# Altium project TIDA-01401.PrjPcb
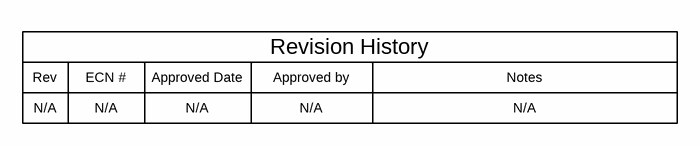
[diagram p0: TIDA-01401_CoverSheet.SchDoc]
CopyrightYear: 2017; PCB_Layout: Zoe Boele; PCB_Rev: E2; PRJ_Customer: Internal Use Only; PRJ_Engineer: Kristen Mogensen; PRJ_Number: TIDA-01401; PRJ_Title: High EMI-Immunity EnDat BoosterPack; SCH_Rev: 1.1; TechSupport: http://www.ti.com/support; TID: 01401
5 sheets, 119 parts. Net scope: global (net labels, ports and power ports of the same name join across sheets).
Board file: TIDA-01401_PCB.PcbDoc
Sheets:
  TIDA-01401_CoverSheet.SchDoc
  TIDA-01401_EVM_Hardware.SchDoc
  TIDA-01401_Interface.SchDoc
  TIDA-01401_PowerSupply.SchDoc
  TIDA-01401_Transceivers.SchDoc

## Sheet TIDA-01401_CoverSheet.SchDoc
size 431 x 279 mm; Date: Not shown in title block; ApprovedBy: Not shown in title block; CheckedBy: Not shown in title block; Author: Not shown in title block; CompanyName: Not shown in title block; Engineer: Not shown in title block; Organization: Not shown in title block; Address1: Not shown in title block; Address2: Not shown in title block; Address3: Not shown in title block; Address4: Not shown in title block; DocumentNumber: 1; Revision: Use project parameter SCH_Rev; SheetNumber: 1; SheetTotal: 3; PageSetup: Record=PageOptions¦CenterHorizontal=True¦CenterVertical=True¦PrintScale=1.00¦XCorrection=1.00¦YCorrection=1.00¦PrintKind=0¦BorderSize=5000000¦LeftOffset=0¦BottomOffset=0¦Orientation=2¦PaperLength=1000¦PaperWidth=1000¦Scale=100¦PaperSource=15¦PrintQuality=600¦MediaType=1¦DitherType=10¦PaperKind=Letter¦PrintScaleMode=1

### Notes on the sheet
- Rev
- N/A
- ECN #
- Approved Date
- Approved by
- Revision History
- Notes

## Sheet TIDA-01401_EVM_Hardware.SchDoc
size 431 x 279 mm; Date: Not shown in title block; ApprovedBy: Not shown in title block; CheckedBy: Not shown in title block; Author: Not shown in title block; CompanyName: Not shown in title block; Engineer: Not shown in title block; Organization: Not shown in title block; Address1: Not shown in title block; Address2: Not shown in title block; Address3: Not shown in title block; Address4: Not shown in title block; DocumentNumber: 1; Revision: Use project parameter SCH_Rev; SheetNumber: 3; SheetTotal: 3; PageSetup: Record=PageOptions¦CenterHorizontal=True¦CenterVertical=True¦PrintScale=1.00¦XCorrection=1.00¦YCorrection=1.00¦PrintKind=0¦BorderSize=5000000¦LeftOffset=0¦BottomOffset=0¦Orientation=2¦PaperLength=1000¦PaperWidth=1000¦Scale=100¦PaperSource=15¦PrintQuality=600¦MediaType=1¦DitherType=10¦PaperKind=Letter¦PrintScaleMode=1
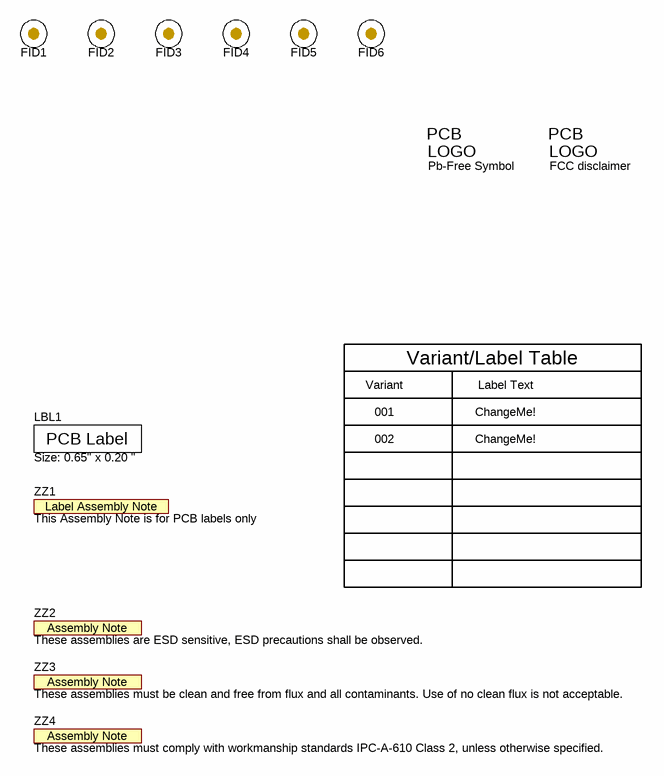
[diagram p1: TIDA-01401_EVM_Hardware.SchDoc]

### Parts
FID1  Fiducial  [Fiducial10-20]  (value not drawn)
FID2  Fiducial  [Fiducial10-20]  (value not drawn)
FID3  Fiducial  [Fiducial10-20]  (value not drawn)
FID4  Fiducial  [Fiducial10-20]  (value not drawn)
FID5  Fiducial  [Fiducial10-20]  (value not drawn)
FID6  Fiducial  [Fiducial10-20]  (value not drawn)
LBL1  Size: 0.65" x 0.20 "  [Label_650x200]
Logo2  Pb-Free Symbol  [Pb-Free_Overlay_Small]  (no BOM)
Logo3  FCC disclaimer  [FCC_disclaimer]  (no BOM)
ZZ1  This Assembly Note is for PCB labels only  [AssemblyNoteLabel]  (no BOM)
ZZ2  These assemblies are ESD sensitive, ESD precautions shall be observed.  [AssemblyNote]  (no BOM)
ZZ3  These assemblies must be clean and free from flux and all contaminants. Use of no clean flux is not acceptable.  [AssemblyNote]  (no BOM)
ZZ4  These assemblies must comply with workmanship standards IPC-A-610 Class 2, unless otherwise specified.  [AssemblyNote]  (no BOM)

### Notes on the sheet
- Variant
- Variant/Label Table
- Label Text
- 001
- 002
- ChangeMe!

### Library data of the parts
FID1-FID6 = Fiducial: Fiducial mark.  There is nothing to buy or mount.; SymbolCreator: codlsc
LBL1 = THT-14-423-10: Thermal Transfer Printable Labels, 0.650" W x 0.200" H - 10,000 per roll; Manufacturer: Brady; SymbolCreator: a0412235; CompType: Label
Logo2 = Pb-Free: SymbolCreator: a0412235
Logo3 = FCC_disclaimer: SymbolCreator: codlsc
ZZ1 = AssemblyNoteLabel: SymbolCreator: a0412235
ZZ2-ZZ4 = AssemblyNote: SymbolCreator: codlsc

## Sheet TIDA-01401_Interface.SchDoc
size 431 x 279 mm; Date: Not shown in title block; ApprovedBy: Not shown in title block; CheckedBy: Not shown in title block; Author: Not shown in title block; CompanyName: Not shown in title block; Engineer: Not shown in title block; Organization: Not shown in title block; Address1: Not shown in title block; Address2: Not shown in title block; Address3: Not shown in title block; Address4: Not shown in title block; DocumentNumber: 1; Revision: Use project parameter SCH_Rev; SheetNumber: 2; SheetTotal: 3; PageSetup: Record=PageOptions¦CenterHorizontal=True¦CenterVertical=True¦PrintScale=0.64¦XCorrection=1.00¦YCorrection=1.00¦PrintKind=0¦BorderSize=5000000¦LeftOffset=0¦BottomOffset=0¦Orientation=2¦PaperLength=1000¦PaperWidth=1000¦Scale=100¦PaperSource=15¦PrintQuality=600¦MediaType=1¦DitherType=10¦PrintScaleMode=1¦PaperKind=8 1/2x11¦PaperIndex=1
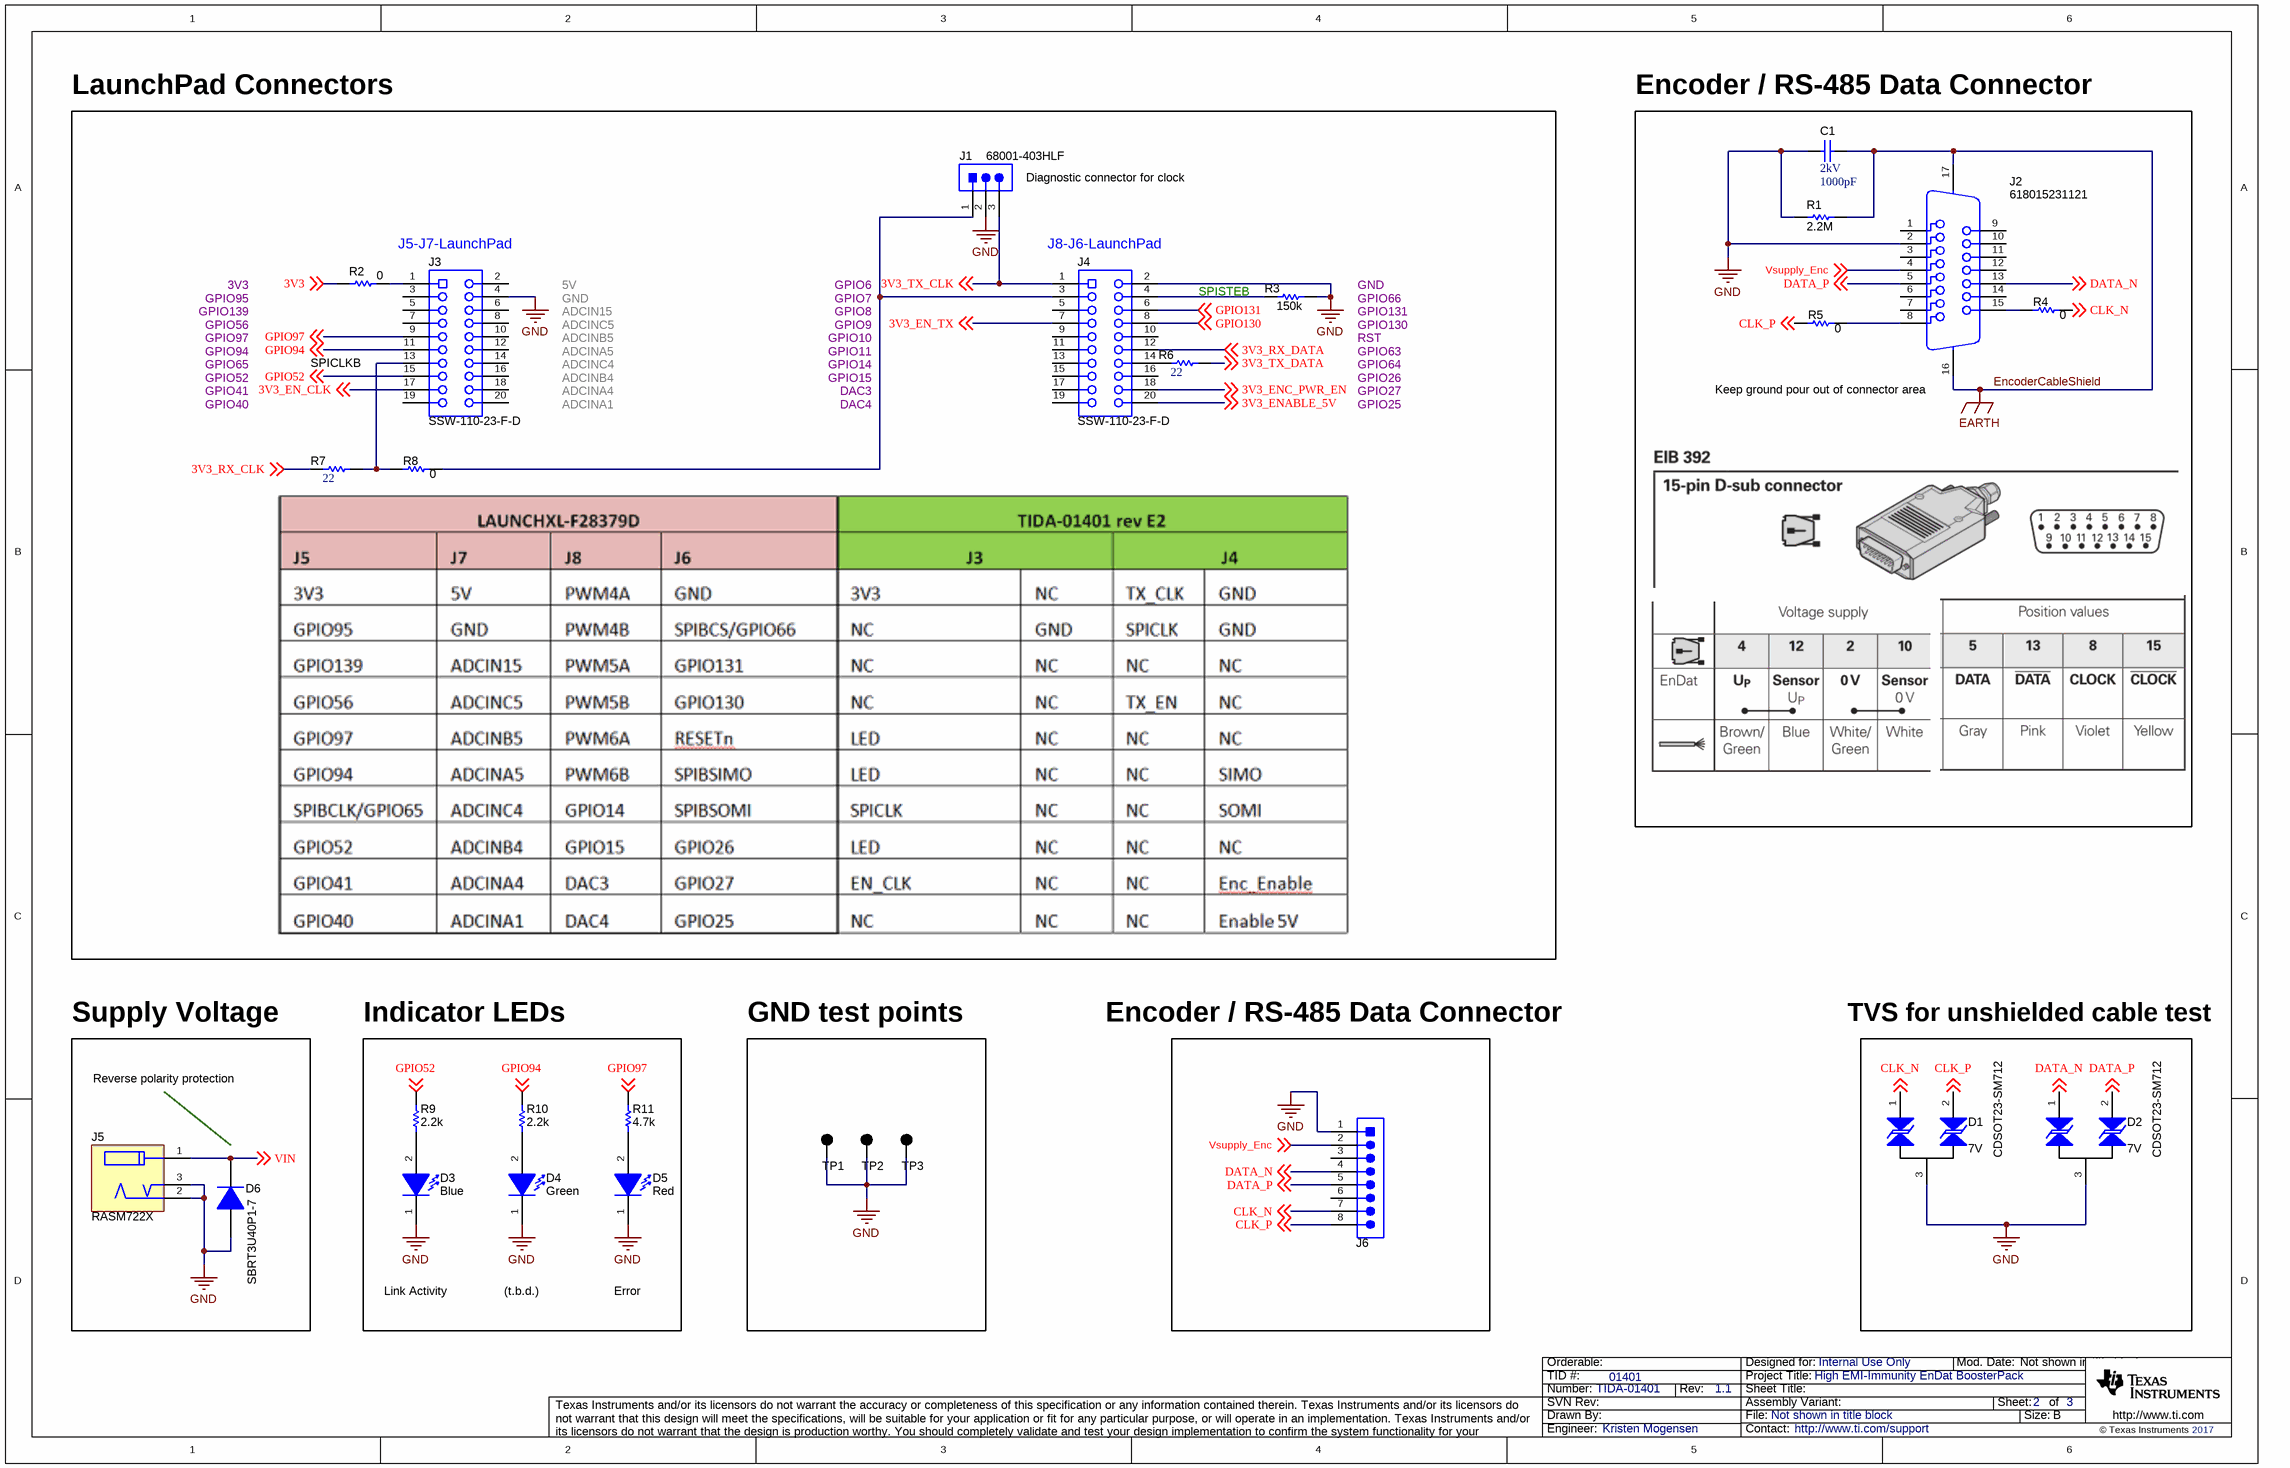
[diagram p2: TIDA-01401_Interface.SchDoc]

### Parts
C1  VDC_V: 2kV  ValueDisplayed: 1000pF  [1812_220]  (hidden comment: 1812GC102KAT1A)
D1  CDSOT23-SM712  value 7V  [SOT-23]
D2  CDSOT23-SM712  value 7V  [SOT-23]
D3  value Blue  [WL-SMCW_Blue]  (hidden comment: 150060BS75000)
D4  value Green  [WL-SMCW_GREEN]  (hidden comment: 150060GS75000)
D5  value Red  [WL-SMCW_RED]  (hidden comment: 150060RS75000)
D6  SBRT3U40P1-7  [PowerDI123]
J1  68001-403HLF  [FCI_68001-403HLF]
J2  618015231121  [Wurth_618015231121]
J3  SSW-110-23-F-D  [CONN_SSW-110-23-F-D]
J4  SSW-110-23-F-D  [CONN_SSW-110-23-F-D]
J5  RASM722X  [Switchcraft_RASM722]
J6  PEC08SAAN  [SULLINS_PEC08SAAN]  (value not drawn)
R1  ValueDisplayed: 2.2M  [1206]  (hidden comment: CRCW12062M20JNEA)
R2  ValueDisplayed: 0  [0603]  (hidden comment: CRCW06030000Z0EA)
R3  ValueDisplayed: 150k  [0402S]  (hidden comment: CRCW0402150KJNED)
R4  ValueDisplayed: 0  [0402S]  (hidden comment: CRCW04020000Z0ED)
R5  ValueDisplayed: 0  [0402S]  (hidden comment: CRCW04020000Z0ED)
R6  ValueDisplayed: 22  [0402S]  (hidden comment: CRCW040222R0JNED)
R7  ValueDisplayed: 22  [0402S]  (hidden comment: CRCW040222R0JNED)
R8  ValueDisplayed: 0  [0402S]  (hidden comment: CRCW04020000Z0ED)
R9  ValueDisplayed: 2.2k  [0402S]  (hidden comment: CRCW04022K20JNED)
R10  ValueDisplayed: 2.2k  [0402S]  (hidden comment: CRCW04022K20JNED)
R11  ValueDisplayed: 4.7k  [0402S]  (hidden comment: CRCW04024K70JNED)
TP1  5001  [Keystone5001]  (value not drawn)
TP2  5001  [Keystone5001]  (value not drawn)
TP3  5001  [Keystone5001]  (value not drawn)

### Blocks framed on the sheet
Keep ground pour out of connector area: C1 J2 R1 R4 R5
Reverse polarity protection: D6 J5

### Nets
EncoderCableShield: C1.1 J2.16(MH1) J2.17(MH2) R1.2  [also labelled EARTH]
GND: C1.2 D1.3 D2.3 D3.1(K) D4.1(K) D5.1(K) D6.2(A) J1.2 J2.2 J3.4 J4.2 J5.2 J5.3 J6.1 R1.1 R3.2 TP1.1 TP2.1 TP3.1
3V3: R2.1 ; off-sheet 3V3
3V3_EN_CLK: J3.17 ; off-sheet 3V3_EN_CLK
3V3_EN_TX: J4.7 ; off-sheet 3V3_EN_TX
3V3_ENABLE_5V: J4.20 ; off-sheet 3V3_ENABLE_5V
3V3_ENC_PWR_EN: J4.18 ; off-sheet 3V3_ENC_PWR_EN
3V3_RX_CLK: R7.1 ; off-sheet 3V3_RX_CLK
3V3_RX_DATA: J4.12 ; off-sheet 3V3_RX_DATA
3V3_TX_CLK: J1.3 J4.1 ; off-sheet 3V3_TX_CLK
3V3_TX_DATA: R6.2 ; off-sheet 3V3_TX_DATA
CLK_N: D1.1 J6.7 R4.2 ; off-sheet CLK_N
CLK_P: D1.2 J6.8 R5.1 ; off-sheet CLK_P
DATA_N: D2.1 J2.13 J6.4 ; off-sheet DATA_N
DATA_P: D2.2 J2.5 J6.5 ; off-sheet DATA_P
GPIO52: J3.15 R9.2 ; off-sheet GPIO52
GPIO94: J3.11 R10.2 ; off-sheet GPIO94
GPIO97: J3.9 R11.2 ; off-sheet GPIO97
GPIO130: J4.8 ; off-sheet GPIO130
GPIO131: J4.6 ; off-sheet GPIO131
VIN: D6.1(K) J5.1 ; off-sheet VIN
Vsupply_Enc: J2.4 J6.2 ; off-sheet Vsupply_Enc
NetD3_2: D3.2(A) R9.1
NetD4_2: D4.2(A) R10.1
NetD5_2: D5.2(A) R11.1
NetJ1_1: J1.1 J4.3 R8.2
NetJ2_8: J2.8 R5.2
NetJ2_15: J2.15 R4.1
NetJ3_1: J3.1 R2.2
NetJ3_13: J3.13 R7.2 R8.1
NetJ4_4: J4.4 R3.1
NetJ4_14: J4.14 R6.1

Not connected (* = marked no-connect by the designer): J2 1 3 6 7 9 10 11 12 14; J3 2 3 5 6 7 8 10 12 14 16 18 19 20; J4 5 9 10 11 13 15 16 17 19; J6 3 6

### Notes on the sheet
- LaunchPad Connectors
- (near C1) Encoder / RS-485 Data Connector
- (near J1) Diagnostic connector for clock
- J5-J7-LaunchPad
- (near J4) J8-J6-LaunchPad
- (near R3) SPISTEB
- SPICLKB
- 3V3
  GPIO95
  GPIO139
  GPIO56
  GPIO97
  GPIO94
  GPIO65
  GPIO52
  GPIO41
  GPIO40
- 5V
  GND
  ADCIN15
  ADCINC5
  ADCINB5
  ADCINA5
  ADCINC4
  ADCINB4
  ADCINA4
  ADCINA1
- GPIO6
  GPIO7
  GPIO8
  GPIO9
  GPIO10
  GPIO11
  GPIO14
  GPIO15
  DAC3
  DAC4
- GND
  GPIO66
  GPIO131
  GPIO130
  RST
  GPIO63
  GPIO64
  GPIO26
  GPIO27
  GPIO25
- Supply Voltage
- Indicator LEDs
- GND test points
- Encoder / RS-485 Data Connector
- TVS for unshielded cable test
- Link Activity
- (t.b.d.)
- Error

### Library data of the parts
C1 = CMP-0064918-2: CAP, CERM, 1000 pF, 2000 V,+/- 10%, X7R, 1812; Manufacturer: AVX; TaMin_C: -55°C; Polarized: N; SizeAreaWB_mm2: 23.1; Value1: Unknown; U/M: EA; Value: 1000pF; TaMax_C: 125°C; SizeZ_mm: 2.2; SizeX_mm: 4.5; SizeY_mm: 3.2; Cap_Case: 1812; Value2: 2000V; SizeArea_mm2: 14.4; CompType: Capacitor; Cap_F: 1nF; AEC Category: Q200
D1 D2 = CDSOT23-SM712: Diode, TVS, Bi, 7 V, SOT-23; Manufacturer: Bourns; SymbolCreator: a0411947; U/M: EA; Vr_V: 7; Value1: W; SizeAreaWB_mm2: 14; SizeArea_mm2: 7.5; SizeX_mm: 2.5; SizeY_mm: 3; SizeZ_mm: 1.1; AEC Category: Q101
D3 = 150060BS75000: LED, Blue, SMD; Manufacturer: Wurth Elektronik; Type: InGaN; Vf_V: 3.2; Value2: 3.2V; Io_A: 0.03; Vr_V: 5; Tjmax_C: 85; Power_TotalModule: 0.105; Value1: 0.105W; Angle: 140; U/M: EA
D4 = 150060GS75000: LED, Green, SMD; Manufacturer: Wurth Elektronik; Type: InGaN; Vf_V: 3.2; Value2: 3.2V; Io_A: 0.02; Tjmax_C: 85; Value1: W; Angle: 140; U/M: EA
D5 = 150060RS75000: LED, Red, SMD; Manufacturer: Wurth Elektronik; Type: AlInGaP; Vf_V: 2; Value2: 2V; Io_A: 0.03; Vr_V: 5; Tjmax_C: 85; Power_TotalModule: 0.072; Value1: 0.072W; Angle: 140; U/M: EA
D6 = SBRT3U40P1-7: Diode, Super Barrier Rectifier, 40 V, 3 A, AEC-Q101, PowerDI123; Manufacturer: Diodes Inc.; U/M: EA; Vf_V: 0.49; Value: 40V; Value1: 3A; Value2: 0.49V; Io_A: 3; Vr_V: 40; TJmax_C: 150; RJC_CperW: 19; SizeAreaWB_mm2: 13.066; SizeArea_mm2: 6.586; SizeX_mm: 3.7; SizeY_mm: 1.78; SizeZ_mm: 0.98; AEC Category: Q101; AEC Qualified: Y
J1 = 68001-403HLF: Header, 2.54mm, 3x1, Tin, TH; Manufacturer: FCI; SymbolCreator: a0799628; Pitch_mm: 2.54; Gender: Male; Shrouded: N; Row_Count: 1; Current_A: 3; Voltage_V: 1500; Cert_CSA: Y
J2 = CMP-0077259-1: Receptacle, D-Sub, 15 Position, R/A, TH; Manufacturer: Wurth Elektronik; Pitch_mm: 2.77; Gender: Female; Cert_UL: Y; Current_A: 3A; Voltage_V: 125V; ContactFinish: Gold; RowSpacing_mm: 2.84; Row_Count: 2
J3 J4 = SSW-110-23-F-D: Connector, Receptacle, 100mil, 10x2, Gold plated, TH; Manufacturer: Samtec; SymbolCreator: a0412235
J5 = RASM722X: Power Jack, 2mm, R/A, SMD; Manufacturer: Switchcraft; SymbolCreator: a0799628
J6 = PEC08SAAN: Header, 100mil, 8x1, Tin, TH; Manufacturer: Sullins Connector Solutions; SymbolCreator: a0411947; Pitch_mm: 2.54; Gender: Male; Shrouded: N; Row_Count: 1; Current_A: 3; Voltage_V: 1800; Cert_UL: Y
R1 = CRCW12062M20JNEA: RES, 2.2 M, 5%, 0.25 W, 1206; Manufacturer: Vishay-Dale; CompType: Resistor; Value: 2.2Meg; Res_ohm: 2200000; Value_Code: 2M20; Tolerance_%: 5; Power_W: 0.25; Value2: 0.25W; VDC_V: 200; TempCo: 200 ppm/C; SizeArea_mm2: 5.12; SizeX_mm: 3.2; SizeY_mm: 1.6; SizeZ_mm: 1.35; EIA_Code: E24; U/M: EA; AEC Category: Q200
R2 = CRCW06030000Z0EA: RES, 0, 5%, 0.1 W, 0603; Manufacturer: Vishay-Dale; CompType: Resistor; Value: 0; Value_Code: 0000; Tolerance_%: 5; Power_W: 0.1; Value2: 0.1W; VDC_V: 75; TempCo: 200 ppm/C; SizeArea_mm2: 1.28; SizeX_mm: 1.6; SizeY_mm: 0.8; SizeZ_mm: 1; EIA_Code: E24; U/M: EA; AEC Category: Q200
R3 = CRCW0402150KJNED: RES, 150 k, 5%, 0.063 W, 0402; Manufacturer: Vishay-Dale; CompType: Resistor; Value: 150k; Res_ohm: 150000; Tolerance_%: 5; Power_W: 0.063; Value2: 0.063W; VDC_V: 50; TempCo: 200 ppm/C; SizeArea_mm2: 0.5; SizeX_mm: 1; SizeZ_mm: 0.6; EIA_Code: E24; U/M: EA; AEC Category: Q200
R4 R5 R8 = CRCW04020000Z0ED: RES, 0, 5%, 0.063 W, 0402; Manufacturer: Vishay-Dale; CompType: Resistor; Value: 0; Value_Code: 0000; Tolerance_%: 5; Power_W: 0.063; Value2: 0.063W; VDC_V: 50; TempCo: 200 ppm/C; SizeArea_mm2: 0.5; SizeX_mm: 1; SizeZ_mm: 0.6; EIA_Code: E24; U/M: EA; AEC Category: Q200
R6 R7 = CMP-0026880-2: RES, 22, 5%, 0.063 W, 0402; Manufacturer: Vishay-Dale; Power_W: 63mW; TempCo: 200 ppm/C; Value_Code: 22R0; U/M: EA; Value: 22; EIA_Code: E24; SizeX_mm: 1; SizeY_mm: 0.5; SizeZ_mm: 0.6; Value2: 0.063W; CompType: Resistor; VDC_V: 50V; AEC Category: Q200
R9 R10 = CRCW04022K20JNED: RES, 2.2 k, 5%, 0.063 W, 0402; Manufacturer: Vishay-Dale; CompType: Resistor; Value: 2.2k; Res_ohm: 2200; Value_Code: 2k20; Tolerance_%: 5; Power_W: 0.063; Value2: 0.063W; VDC_V: 50; TempCo: 200 ppm/C; SizeArea_mm2: 0.5; SizeX_mm: 1; SizeZ_mm: 0.6; EIA_Code: E24; U/M: EA; AEC Category: Q200
R11 = CRCW04024K70JNED: RES, 4.7 k, 5%, 0.063 W, 0402; Manufacturer: Vishay-Dale; CompType: Resistor; Value: 4.7k; Res_ohm: 4700; Value_Code: 4k70; Tolerance_%: 5; Power_W: 0.063; Value2: 0.063W; VDC_V: 50; TempCo: 200 ppm/C; SizeArea_mm2: 0.5; SizeX_mm: 1; SizeZ_mm: 0.6; EIA_Code: E24; U/M: EA; AEC Category: Q200
TP1-TP3 = 5001: Test Point, Miniature, Black, TH; Manufacturer: Keystone; CompType: Test Point Loop; ContactFinish: Silver

## Sheet TIDA-01401_PowerSupply.SchDoc
size 431 x 279 mm; Date: Not shown in title block; ApprovedBy: Not shown in title block; CheckedBy: Not shown in title block; Author: Not shown in title block; CompanyName: Not shown in title block; Engineer: Not shown in title block; Organization: Not shown in title block; Address1: Not shown in title block; Address2: Not shown in title block; Address3: Not shown in title block; Address4: Not shown in title block; DocumentNumber: 1; Revision: Use project parameter SCH_Rev; SheetNumber: 2; SheetTotal: 3; PageSetup: Record=PageOptions¦CenterHorizontal=True¦CenterVertical=True¦PrintScale=1.00¦XCorrection=1.00¦YCorrection=1.00¦PrintKind=0¦BorderSize=5000000¦LeftOffset=0¦BottomOffset=0¦Orientation=2¦PaperLength=1000¦PaperWidth=1000¦Scale=100¦PaperSource=15¦PrintQuality=600¦MediaType=1¦DitherType=10¦PaperKind=Letter¦PrintScaleMode=1
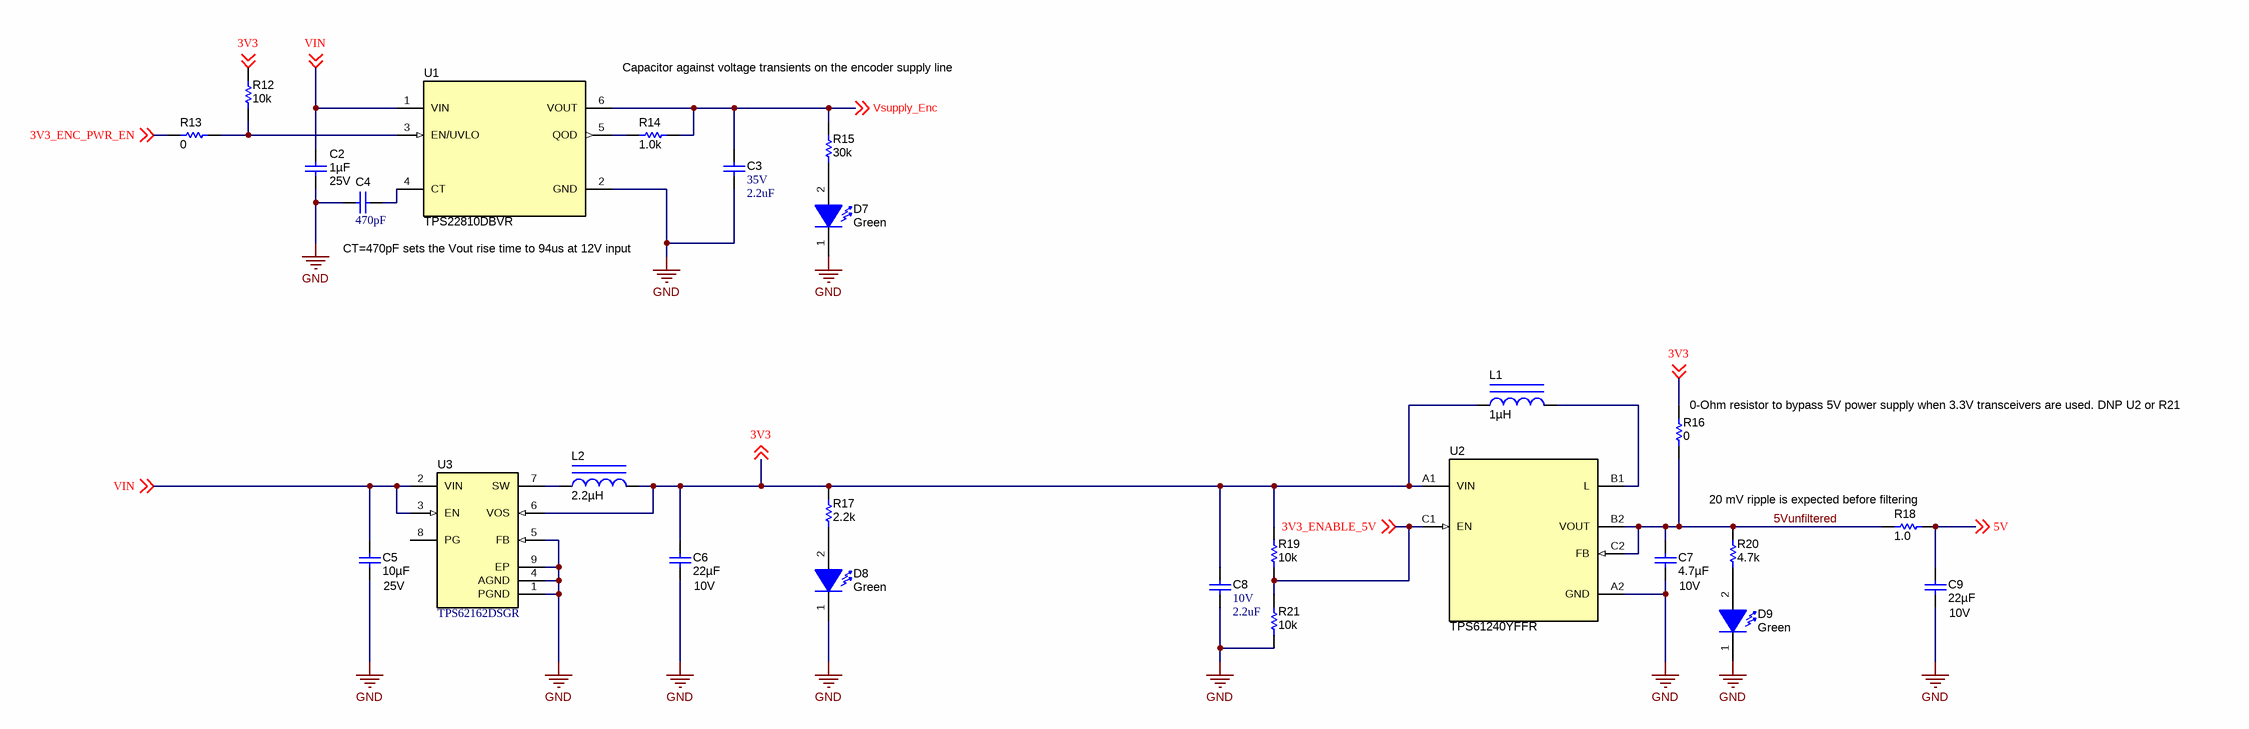
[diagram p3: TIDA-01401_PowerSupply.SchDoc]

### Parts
C2  ValueDisplayed: 1µF  Value2: 25V  [0603S]  (hidden comment: 885012206076)
C3  VDC_V: 35V  ValueDisplayed: 2.2uF  [0402_070]  (hidden comment: GRM155R6YA225ME11D)
C4  ValueDisplayed: 470pF  [0402S]  (hidden comment: GRM155R71H471KA01D)
C5  ValueDisplayed: 10µF  Value2: 25V  [0603S]  (hidden comment: C1608X5R1E106M080AC)
C6  ValueDisplayed: 22µF  Value2: 10V  [0603S]  (hidden comment: GRM187R61A226ME15D)
C7  ValueDisplayed: 4.7µF  Value2: 10V  [0402S]  (hidden comment: C1005X5R1A475K050BC)
C8  VDC_V: 10V  ValueDisplayed: 2.2uF  [0402S]  (hidden comment: 885012105013)
C9  ValueDisplayed: 22µF  Value2: 10V  [0603S]  (hidden comment: GRM187R61A226ME15D)
D7  value Green  [WL-SMCW_GREEN]  (hidden comment: 150060GS75000)
D8  value Green  [WL-SMCW_GREEN]  (hidden comment: 150060GS75000)
D9  value Green  [WL-SMCW_GREEN]  (hidden comment: 150060GS75000)
L1  ValueDisplayed: 1µH  [WE-PMI-0805_1]  (hidden comment: 74479775210)
L2  ValueDisplayed: 2.2µH  [XFL3012]  (hidden comment: XFL3012-222MEB)
R12  ValueDisplayed: 10k  [0402]  (hidden comment: CRCW040210K0JNED)
R13  ValueDisplayed: 0  [0402]  (hidden comment: CRCW04020000Z0ED)
R14  ValueDisplayed: 1.0k  [0603S]  (hidden comment: CRCW06031K00JNEA)
R15  ValueDisplayed: 30k  [0402S]  (hidden comment: CRCW040230K0JNED)
R16  ValueDisplayed: 0  [0402]  (hidden comment: CRCW04020000Z0ED)
R17  ValueDisplayed: 2.2k  [0402S]  (hidden comment: CRCW04022K20JNED)
R18  ValueDisplayed: 1.0  [0603S]  (hidden comment: CRCW06031R00JNEA)
R19  ValueDisplayed: 10k  [0402]  (hidden comment: CRCW040210K0JNED)
R20  ValueDisplayed: 4.7k  [0402S]  (hidden comment: CRCW04024K70JNED)
R21  ValueDisplayed: 10k  [0402]  (hidden comment: CRCW040210K0JNED)
U1  TPS22810DBVR  [DBV0006A_N]
U2  TPS61240YFFR  [YFF0006AEAE]
U3  TPS62162DSGR  [DSG0008A]

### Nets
GND: C2.2 C3.2 C4.1 C5.2 C6.2 C7.2 C8.2 C9.2 D7.1(K) D8.1(K) D9.1(K) R21.1 U1.2(GND) U2.A2(GND) U3.1(PGND) U3.4(AGND) U3.5(FB) U3.9(EP)
3V3: C6.1 C8.1 L1.1 L2.2 R12.2 R16.2 R17.2 R19.2 U2.A1(VIN) U3.6(VOS) ; off-sheet 3V3
3V3_ENABLE_5V: R19.1 R21.2 U2.C1(EN) ; off-sheet 3V3_ENABLE_5V
3V3_ENC_PWR_EN: R13.1 ; off-sheet 3V3_ENC_PWR_EN
5V: C9.1 R18.2 ; off-sheet 5V
5Vunfiltered: C7.1 R16.1 R18.1 R20.2 U2.B2(VOUT) U2.C2(FB)
VIN: C2.1 C5.1 U1.1(VIN) U3.2(VIN) U3.3(EN) ; off-sheet VIN
Vsupply_Enc: C3.1 R14.2 R15.1 U1.6(VOUT) ; off-sheet Vsupply_Enc
NetC4_2: C4.2 U1.4(CT)
NetD7_2: D7.2(A) R15.2
NetD8_2: D8.2(A) R17.1
NetD9_2: D9.2(A) R20.1
NetL1_2: L1.2 U2.B1(L)
NetL2_1: L2.1 U3.7(SW)
NetR12_1: R12.1 R13.2 U1.3(EN/UVLO)
NetR14_1: R14.1 U1.5(QOD)

Not connected (* = marked no-connect by the designer): U3 8(PG)

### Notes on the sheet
- (near U1) Capacitor against voltage transients on the encoder supply line
- CT=470pF sets the Vout rise time to 94us at 12V input
- (near R16) 0-Ohm resistor to bypass 5V power supply when 3.3V transceivers are used. DNP U2 or R21
- 20 mV ripple is expected before filtering

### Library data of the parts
C2 = 885012206076: CAP, CERM, 1 µF, 25 V, +/- 10%, X7R, 0603; Manufacturer: Wurth Elektronik; Polarized: N; CompType: Capacitor; Value: 1uF; U/M: EA; Cap_F: 0.000001; Tolerance_%: 10; Value1: Unknown; VDC_V: 25; TaMin_C: -55; TaMax_C: 125; Cap_Case: 0603; SizeArea_mm2: 1.28; SizeAreaWB_mm2: 4.68; SizeX_mm: 1.6; SizeY_mm: 0.8; SizeZ_mm: 1; AEC Category: Q200
C3 = CMP-0006621-2: CAP, CERM, 2.2 uF, 35 V, +/- 20%, X5R, 0402; Manufacturer: MuRata; TaMin_C: -55°C; Polarized: N; SizeAreaWB_mm2: 3; Value1: Unknown; U/M: EA; Value: 2.2uF; TaMax_C: 85°C; SizeZ_mm: 0.7; SizeX_mm: 1; SizeY_mm: 0.5; Cap_Case: 0402; CompType: Capacitor; Cap_F: 2.2µF; AEC Category: Q200
C4 = CMP-0006691-2: CAP, CERM, 470 pF, 50 V, +/- 10%, X7R, 0402; Manufacturer: MuRata; TaMin_C: -55°C; Polarized: N; SizeAreaWB_mm2: 3; Value1: Unknown; U/M: EA; Value: 470pF; TaMax_C: 125°C; SizeZ_mm: 0.6; SizeX_mm: 1; SizeY_mm: 0.5; Cap_Case: 0402; Value2: 50V; CompType: Capacitor; AEC Category: Q200
C5 = C1608X5R1E106M080AC: CAP, CERM, 10 µF, 25 V, +/- 20%, X5R, 0603; Manufacturer: TDK; Polarized: N; CompType: Capacitor; Value: 10uF; U/M: EA; Cap_F: 0.00001; Tolerance_%: 20; ESR_ohm: 0.004639; Value1: 0.004639 ohm; VDC_V: 25; IRMS_A: 2.41407; TaMin_C: -55; TaMax_C: 85; Cap_Case: 0603; SizeArea_mm2: 1.28; SizeAreaWB_mm2: 4.68; SizeX_mm: 1.6; SizeY_mm: 0.8; SizeZ_mm: 1; AEC Category: Q200
C6 C9 = GRM187R61A226ME15D: CAP, CERM, 22 µF, 10 V, +/- 20%, X5R, 0603; Manufacturer: MuRata; Polarized: N; CompType: Capacitor; Value: 22uF; U/M: EA; Cap_F: 0.000022; Tolerance_%: 20; Value1: Unknown; VDC_V: 10; TaMin_C: -55; TaMax_C: 85; Cap_Case: 0603; SizeArea_mm2: 1.28; SizeAreaWB_mm2: 4.68; SizeX_mm: 1.6; SizeY_mm: 0.8; SizeZ_mm: 1; AEC Category: Q200
C7 = C1005X5R1A475K050BC: CAP, CERM, 4.7 µF, 10 V, +/- 10%, X5R, 0402; Manufacturer: TDK; Polarized: N; CompType: Capacitor; Value: 4.7uF; U/M: EA; Cap_F: 0.0000047; Tolerance_%: 10; ESR_ohm: 0.003417; Value1: 0.003417 ohm; IRMS_A: 2.7063; TaMin_C: -55; TaMax_C: 85; Cap_Case: 0402_065; SizeArea_mm2: 0.5; SizeAreaWB_mm2: 3; SizeX_mm: 1; SizeZ_mm: 0.65; AEC Category: Q200
C8 = CMP-0006222-2: CAP, CERM, 2.2 uF, 10 V, +/- 20%, X5R, 0402; Manufacturer: Wurth Elektronik; TaMin_C: -55°C; Polarized: N; SizeAreaWB_mm2: 3; Value1: Unknown; U/M: EA; Value: 2.2uF; TaMax_C: 85°C; SizeZ_mm: 0.6; SizeX_mm: 1; SizeY_mm: 0.5; Cap_Case: 0402; CompType: Capacitor; Cap_F: 2.2µF; AEC Category: Q200
D7-D9 = 150060GS75000: as D4 on sheet TIDA-01401_Interface
L1 = 74479775210: Inductor, Shielded Drum Core, Metal Composite, 1 µH, 0.7 A, 0.1 ohm, SMD; Manufacturer: Wurth Elektronik; Value: 1uH; Ind_H: 1.0E-6; Imax_A: 0.7; Irms: 1.1A @ 40C rise; Isat: 0.7A @ 30% inductance drop; DCR_ohm: 0.1; Value1: 0.1 ohm; Value2: 0.7A; SizeAreaWB_mm2: 6.6; SizeArea_mm2: 2.4; SizeX_mm: 2; SizeY_mm: 1.2; SizeZ_mm: 1; AEC Category: Q200
L2 = XFL3012-222MEB: Inductor, Shielded, Composite, 2.2 µH, 1.6 A, 0.08 ohm, SMD; Manufacturer: Coilcraft; Value: 2.2uH; Ind_H: 2.2E-6; Imax_A: 1.6; Irms: 1.9A @ 40C rise; Isat: 1.6A @ 30% inductance drop; DCR_ohm: 0.08; Value2: 1.6A; SizeAreaWB_mm2: 16; SizeArea_mm2: 9; SizeX_mm: 3; SizeZ_mm: 1.2; AEC Category: Q200
R12 R19 R21 = CRCW040210K0JNED: RES, 10 k, 5%, 0.063 W, 0402; Manufacturer: Vishay-Dale; CompType: Resistor; Value: 10k; Res_ohm: 10000; Value_Code: 10k0; Tolerance_%: 5; Power_W: 0.063; Value2: 0.063W; VDC_V: 50; TempCo: 200 ppm/C; SizeArea_mm2: 0.5; SizeX_mm: 1; SizeZ_mm: 0.6; EIA_Code: E24; U/M: EA; AEC Category: Q200
R13 R16 = CRCW04020000Z0ED: as R4 on sheet TIDA-01401_Interface
R14 = CRCW06031K00JNEA: RES, 1.0 k, 5%, 0.1 W, 0603; Manufacturer: Vishay-Dale; CompType: Resistor; Value: 1.0k; Res_ohm: 1000; Value_Code: 1k00; Tolerance_%: 5; Power_W: 0.1; Value2: 0.1W; VDC_V: 75; TempCo: 200 ppm/C; SizeArea_mm2: 1.28; SizeX_mm: 1.6; SizeY_mm: 0.8; SizeZ_mm: 1; EIA_Code: E24; U/M: EA; AEC Category: Q200
R15 = CRCW040230K0JNED: RES, 30 k, 5%, 0.063 W, 0402; Manufacturer: Vishay-Dale; CompType: Resistor; Value: 30k; Res_ohm: 30000; Value_Code: 30k0; Tolerance_%: 5; Power_W: 0.063; Value2: 0.063W; VDC_V: 50; TempCo: 200 ppm/C; SizeArea_mm2: 0.5; SizeX_mm: 1; SizeZ_mm: 0.6; EIA_Code: E24; U/M: EA; AEC Category: Q200
R17 = CRCW04022K20JNED: as R9 on sheet TIDA-01401_Interface
R18 = CRCW06031R00JNEA: RES, 1.0, 5%, 0.1 W, 0603; Manufacturer: Vishay-Dale; CompType: Resistor; Value: 1.0; Res_ohm: 1; Value_Code: 1R00; Tolerance_%: 5; Power_W: 0.1; Value2: 0.1W; VDC_V: 75; TempCo: 200 ppm/C; SizeArea_mm2: 1.28; SizeX_mm: 1.6; SizeY_mm: 0.8; EIA_Code: E24; U/M: EA; AEC Category: Q200
R20 = CRCW04024K70JNED: as R11 on sheet TIDA-01401_Interface
U1 = TPS22810DBVR: 2.7-18-V, 2-A, 79-mΩ On-Resistance Load Switch with Thermal Protection, DBV0006A (SOT-23-6); Alternate PartNumber: TPS22810DBVT; Manufacturer: Texas Instruments; SymbolCreator: Altium; SizeArea_mm2: 8.12; SizeAreaWB_mm2: 14.82; SizeX_mm: 2.8; SizeY_mm: 2.9; SizeZ_mm: 1.45; CompType: IC; U/M: EA
U2 = TPS61240YFFR: 3.5-MHz High Efficiency Step-Up Converter, YFF0006AEAE (DSBGA-6); Alternate PartNumber: TPS61240YFFT; Manufacturer: Texas Instruments; SymbolCreator: Altium; SizeArea_mm2: 1.076848; SizeAreaWB_mm2: 4.190848; SizeX_mm: 0.856; SizeY_mm: 1.258; SizeZ_mm: 0.625; CompType: IC; U/M: EA
U3 = TPS62162DSGR: Buck Step Down Regulator with 3 to 17 V Input and 3.3 V Output, -40 to 85 degC, 8-Pin WSON (DSG), Green (RoHS & no Sb/Br); Manufacturer: Texas Instruments; Alternate PartNumber: Equivalent; Duty Cycle(Max)(%): 100; Iout(Max)(A): 1; Iq(Typ)(mA): 0.017; Preset Vout(V): 3.3; Rating: Catalog; SubFamily: Step-Down Regulator; Switch Current Limit(Typ)(A): 1.8; Synchronous Rectification: TRUE; Vin(Max)(V): 17; Vin(Min)(V): 3

## Sheet TIDA-01401_Transceivers.SchDoc
size 431 x 279 mm; Date: Not shown in title block; ApprovedBy: Not shown in title block; CheckedBy: Not shown in title block; Author: Not shown in title block; CompanyName: Not shown in title block; Engineer: Not shown in title block; Organization: Not shown in title block; Address1: Not shown in title block; Address2: Not shown in title block; Address3: Not shown in title block; Address4: Not shown in title block; DocumentNumber: 1; Revision: Use project parameter SCH_Rev; SheetNumber: 2; SheetTotal: 3; PageSetup: Record=PageOptions¦CenterHorizontal=True¦CenterVertical=True¦PrintScale=0.91¦XCorrection=1.00¦YCorrection=1.00¦PrintKind=0¦BorderSize=5000000¦LeftOffset=0¦BottomOffset=0¦Orientation=2¦PaperLength=1000¦PaperWidth=1000¦Scale=100¦PaperSource=15¦PrintQuality=-3¦MediaType=1¦DitherType=10¦PrintScaleMode=1¦PaperKind=A4¦PaperIndex=9
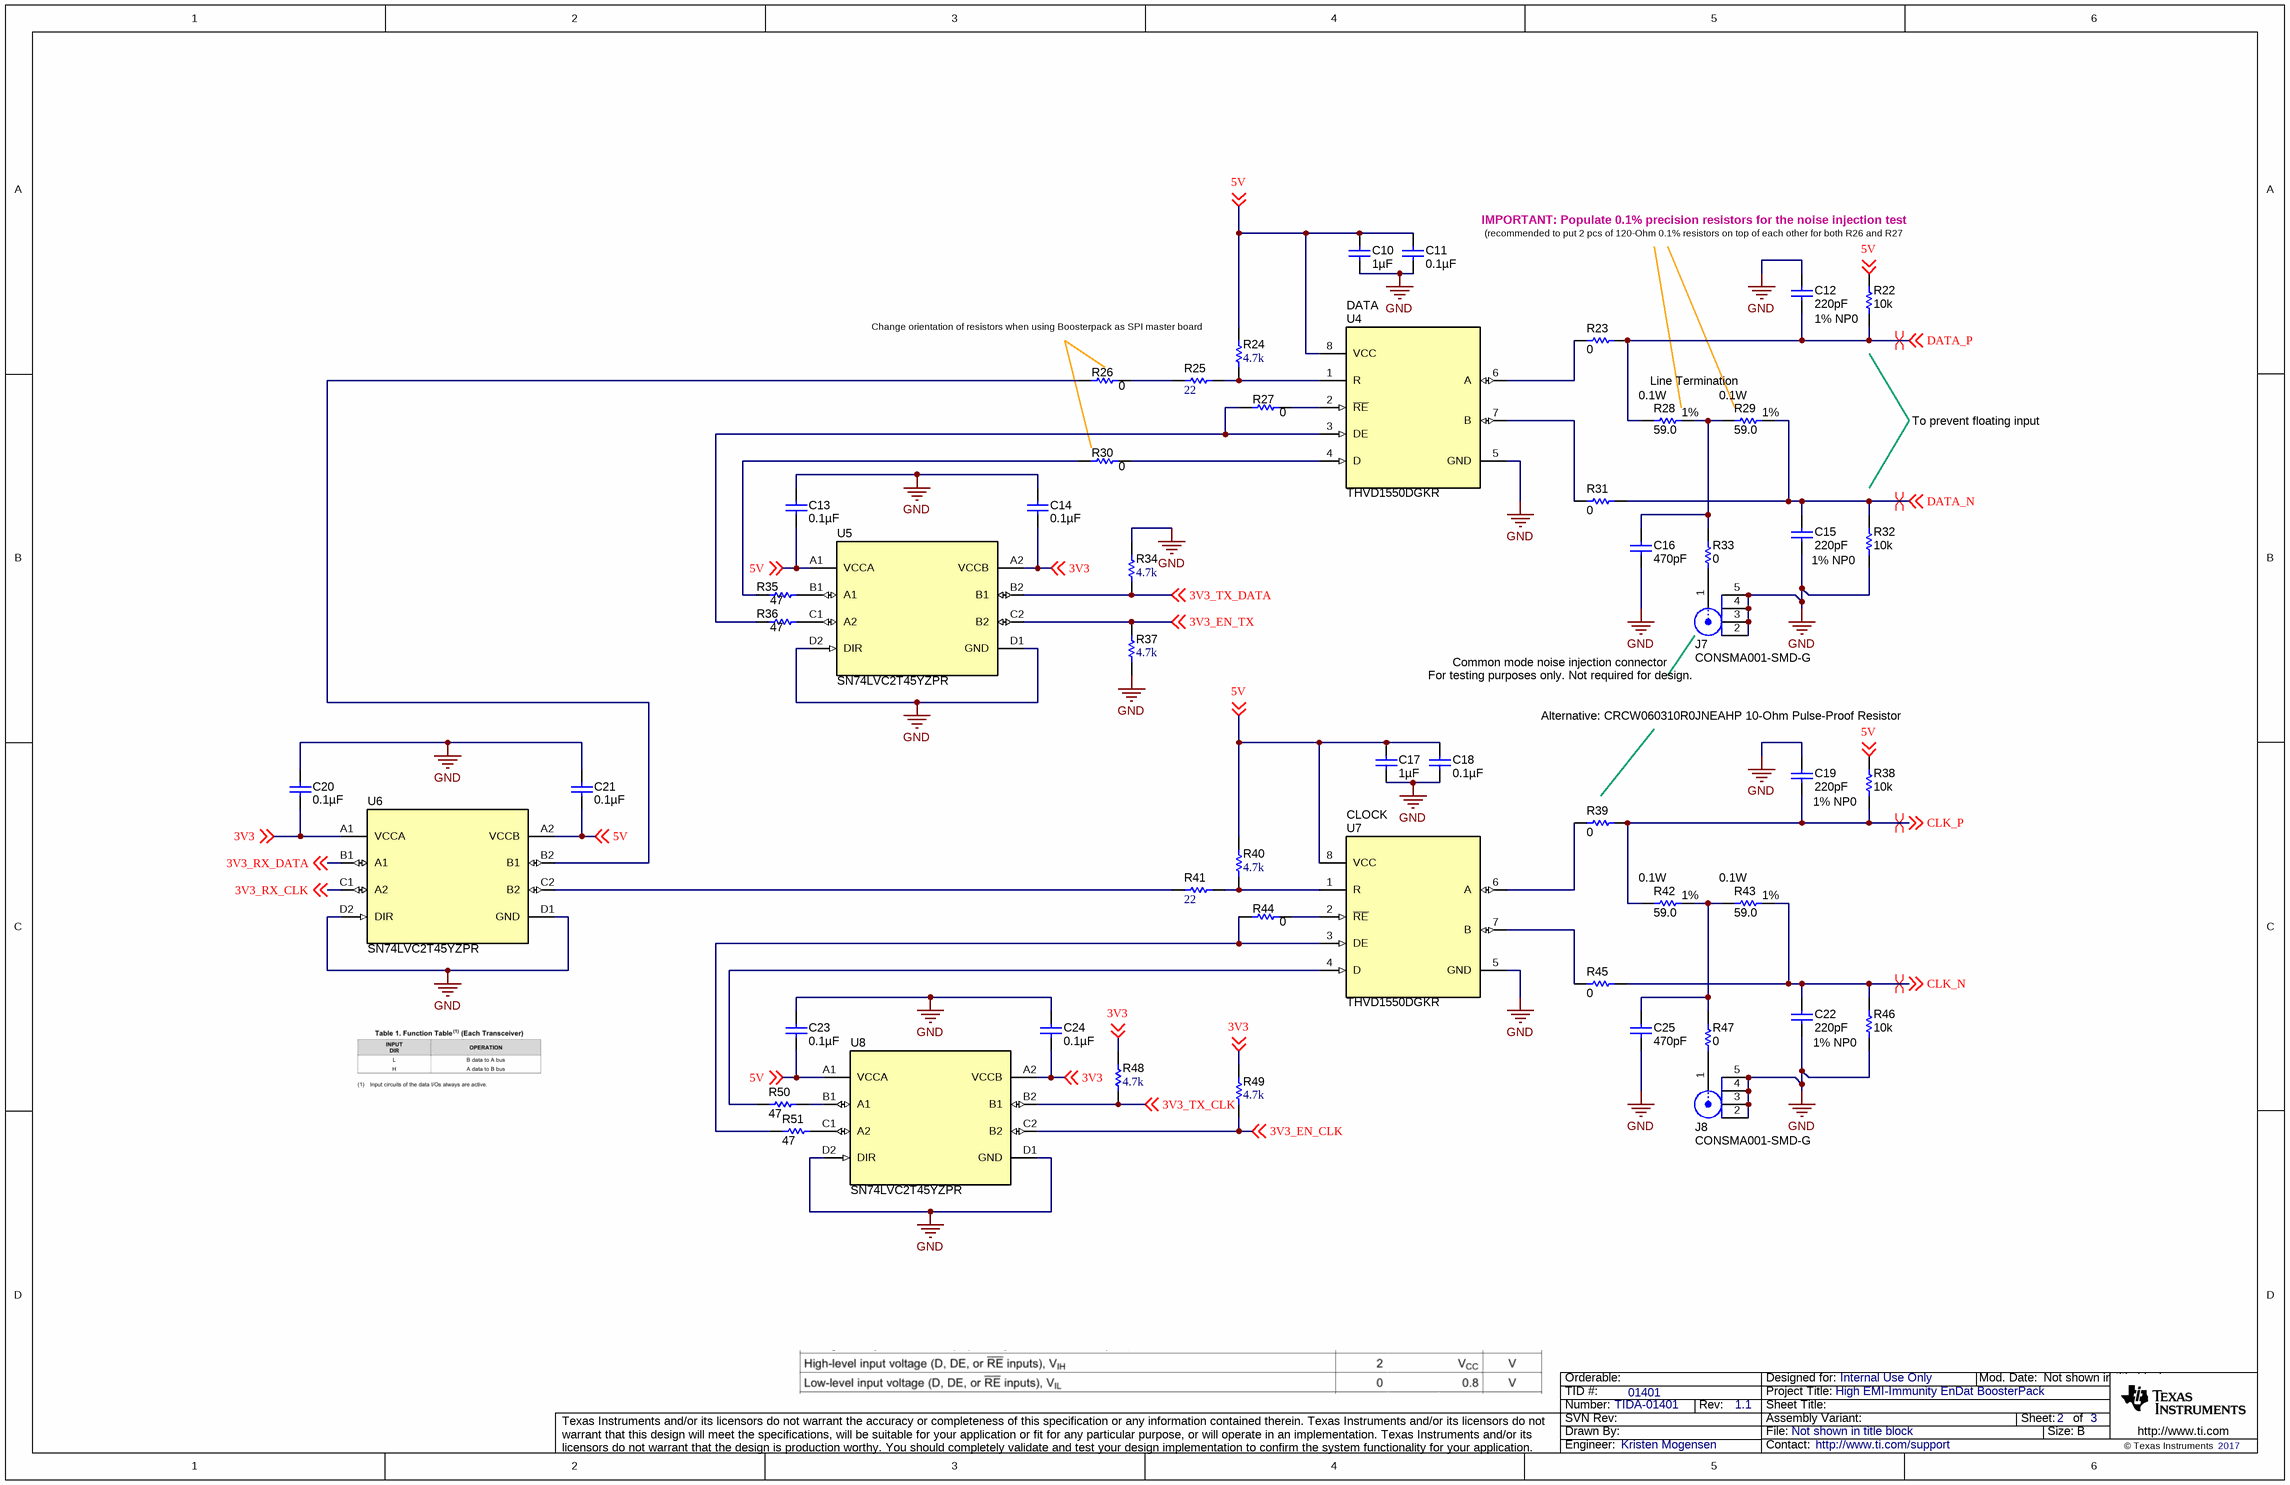
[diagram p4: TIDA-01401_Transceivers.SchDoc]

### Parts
C10  ValueDisplayed: 1µF  [0402S]  (hidden comment: GRM155R61A105KE15D)
C11  ValueDisplayed: 0.1µF  [0402S]  (hidden comment: 885012205037)
C12  ValueDisplayed: 220pF  [0603S]  (hidden comment: 06035A221FAT2A)
C13  ValueDisplayed: 0.1µF  [0402S]  (hidden comment: 885012205037)
C14  ValueDisplayed: 0.1µF  [0402S]  (hidden comment: 885012205037)
C15  ValueDisplayed: 220pF  [0603S]  (hidden comment: 06035A221FAT2A)
C16  ValueDisplayed: 470pF  [0603S]  (hidden comment: 885012206081)
C17  ValueDisplayed: 1µF  [0402S]  (hidden comment: GRM155R61A105KE15D)
C18  ValueDisplayed: 0.1µF  [0402S]  (hidden comment: 885012205037)
C19  ValueDisplayed: 220pF  [0603S]  (hidden comment: 06035A221FAT2A)
C20  ValueDisplayed: 0.1µF  [0402S]  (hidden comment: 885012205037)
C21  ValueDisplayed: 0.1µF  [0402S]  (hidden comment: 885012205037)
C22  ValueDisplayed: 220pF  [0603S]  (hidden comment: 06035A221FAT2A)
C23  ValueDisplayed: 0.1µF  [0402S]  (hidden comment: 885012205037)
C24  ValueDisplayed: 0.1µF  [0402S]  (hidden comment: 885012205037)
C25  ValueDisplayed: 470pF  [0603S]  (hidden comment: 885012206081)
J7  CONSMA001-SMD-G  [Linx_CONSMA001-SMD-G]
J8  CONSMA001-SMD-G  [Linx_CONSMA001-SMD-G]
R22  ValueDisplayed: 10k  [0603S]  (hidden comment: CRCW060310K0JNEA)
R23  ValueDisplayed: 0  [0603S]  (hidden comment: CRCW06030000Z0EA)
R24  ValueDisplayed: 4.7k  [0402S]  (hidden comment: CRCW04024K70JNED)
R25  ValueDisplayed: 22  [0402S]  (hidden comment: CRCW040222R0JNED)
R26  ValueDisplayed: 0  [0402S]  (hidden comment: CRCW04020000Z0ED)
R27  ValueDisplayed: 0  [0402S]  (hidden comment: CRCW04020000Z0ED)
R28  ValueDisplayed: 59.0  Value1: 1%  Value2: 0.1W  [0603S]  (hidden comment: RC0603FR-0759RL)
R29  ValueDisplayed: 59.0  Value1: 1%  Value2: 0.1W  [0603S]  (hidden comment: RC0603FR-0759RL)
R30  ValueDisplayed: 0  [0402S]  (hidden comment: CRCW04020000Z0ED)
R31  ValueDisplayed: 0  [0603S]  (hidden comment: CRCW06030000Z0EA)
R32  ValueDisplayed: 10k  [0603S]  (hidden comment: CRCW060310K0JNEA)
R33  ValueDisplayed: 0  [0402S]  (hidden comment: CRCW04020000Z0ED)
R34  ValueDisplayed: 4.7k  [0402S]  (hidden comment: CRCW04024K70JNED)
R35  ValueDisplayed: 47  [0402S]  (hidden comment: CRCW040247R0JNED)
R36  ValueDisplayed: 47  [0402S]  (hidden comment: CRCW040247R0JNED)
R37  ValueDisplayed: 4.7k  [0402S]  (hidden comment: CRCW04024K70JNED)
R38  ValueDisplayed: 10k  [0603S]  (hidden comment: CRCW060310K0JNEA)
R39  ValueDisplayed: 0  [0603S]  (hidden comment: CRCW06030000Z0EA)
R40  ValueDisplayed: 4.7k  [0402S]  (hidden comment: CRCW04024K70JNED)
R41  ValueDisplayed: 22  [0402S]  (hidden comment: CRCW040222R0JNED)
R42  ValueDisplayed: 59.0  Value1: 1%  Value2: 0.1W  [0603S]  (hidden comment: RC0603FR-0759RL)
R43  ValueDisplayed: 59.0  Value1: 1%  Value2: 0.1W  [0603S]  (hidden comment: RC0603FR-0759RL)
R44  ValueDisplayed: 0  [0402S]  (hidden comment: CRCW04020000Z0ED)
R45  ValueDisplayed: 0  [0603S]  (hidden comment: CRCW06030000Z0EA)
R46  ValueDisplayed: 10k  [0603S]  (hidden comment: CRCW060310K0JNEA)
R47  ValueDisplayed: 0  [0402S]  (hidden comment: CRCW04020000Z0ED)
R48  ValueDisplayed: 4.7k  [0402S]  (hidden comment: CRCW04024K70JNED)
R49  ValueDisplayed: 4.7k  [0402]  (hidden comment: CRCW04024K70JNED)
R50  ValueDisplayed: 47  [0402S]  (hidden comment: CRCW040247R0JNED)
R51  ValueDisplayed: 47  [0402S]  (hidden comment: CRCW040247R0JNED)
U4  THVD1550DGKR  [DGK0008A_N]
U5  SN74LVC2T45YZPR  [YZP0008ADAD]
U6  SN74LVC2T45YZPR  [YZP0008ADAD]
U7  THVD1550DGKR  [DGK0008A_N]
U8  SN74LVC2T45YZPR  [YZP0008ADAD]

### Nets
GND: C10.2 C11.2 C12.1 C13.1 C14.1 C15.2 C16.2 C17.2 C18.2 C19.1 C20.1 C21.1 C22.2 C23.1 C24.1 C25.2 J7.2 J7.3 J7.4 J7.5 J8.2 J8.3 J8.4 J8.5 R32.1 R34.2 R37.1 R46.1 U4.5(GND) U5.D1(GND) U5.D2(DIR) U6.D1(GND) U6.D2(DIR) U7.5(GND) U8.D1(GND) U8.D2(DIR)
3V3: C14.2 C20.2 C24.2 R48.2 R49.2 U5.A2(VCCB) U6.A1(VCCA) U8.A2(VCCB) ; off-sheet 3V3
3V3_EN_CLK: R49.1 U8.C2(B2) ; off-sheet 3V3_EN_CLK
3V3_EN_TX: R37.2 U5.C2(B2) ; off-sheet 3V3_EN_TX
3V3_RX_CLK: U6.C1(A2) ; off-sheet 3V3_RX_CLK
3V3_RX_DATA: U6.B1(A1) ; off-sheet 3V3_RX_DATA
3V3_TX_CLK: R48.1 U8.B2(B1) ; off-sheet 3V3_TX_CLK
3V3_TX_DATA: R34.1 U5.B2(B1) ; off-sheet 3V3_TX_DATA
5V: C10.1 C11.1 C13.2 C17.1 C18.1 C21.2 C23.2 R22.2 R24.2 R38.2 R40.2 U4.8(VCC) U5.A1(VCCA) U6.A2(VCCB) U7.8(VCC) U8.A1(VCCA) ; off-sheet 5V
CLK_N: C22.1 R43.2 R45.2 R46.2 ; off-sheet CLK_N
CLK_P: C19.2 R38.1 R39.2 R42.1 ; off-sheet CLK_P
DATA_N: C15.1 R29.2 R31.2 R32.2 ; off-sheet DATA_N
DATA_P: C12.2 R22.1 R23.2 R28.1 ; off-sheet DATA_P
NetC16_1: C16.1 R28.2 R29.1 R33.2
NetC25_1: C25.1 R42.2 R43.1 R47.2
NetJ7_1: J7.1 R33.1
NetJ8_1: J8.1 R47.1
NetR23_1: R23.1 U4.6(A)
NetR24_1: R24.1 R25.2 U4.1(R)
NetR25_1: R25.1 R26.2
NetR26_1: R26.1 U6.B2(B1)
NetR27_1: R27.1 R36.1 U4.3(DE)
NetR27_2: R27.2 U4.2(~{RE})
NetR30_1: R30.1 R35.1
NetR30_2: R30.2 U4.4(D)
NetR31_1: R31.1 U4.7(B)
NetR35_2: R35.2 U5.B1(A1)
NetR36_2: R36.2 U5.C1(A2)
NetR39_1: R39.1 U7.6(A)
NetR40_1: R40.1 R41.2 U7.1(R)
NetR41_1: R41.1 U6.C2(B2)
NetR44_1: R44.1 R51.1 U7.3(DE)
NetR44_2: R44.2 U7.2(~{RE})
NetR45_1: R45.1 U7.7(B)
NetR50_1: R50.1 U7.4(D)
NetR50_2: R50.2 U8.B1(A1)
NetR51_2: R51.2 U8.C1(A2)

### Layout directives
differential pair: CLK_N, CLK_P, DATA_N, DATA_P

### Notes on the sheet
- IMPORTANT: Populate 0.1% precision resistors for the noise injection test
- (recommended to put 2 pcs of 120-Ohm 0.1% resistors on top of each other for both R26 and R27
- (near R24) Change orientation of resistors when using Boosterpack as SPI master board
- DATA
- 1% NP0
- Line Termination
- To prevent floating input
- (near J7) Common mode noise injection connector
- (near J7) For testing purposes only. Not required for design.
- Alternative: CRCW060310R0JNEAHP 10-Ohm Pulse-Proof Resistor
- CLOCK

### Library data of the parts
C10 C17 = GRM155R61A105KE15D: CAP, CERM, 1 µF, 10 V, +/- 10%, X5R, 0402; Manufacturer: MuRata; Polarized: N; CompType: Capacitor; Value: 1uF; U/M: EA; Cap_F: 0.000001; Tolerance_%: 10; Value1: Unknown; Value2: 10V; TaMin_C: -55; TaMax_C: 85; Cap_Case: 0402; SizeArea_mm2: 0.5; SizeAreaWB_mm2: 3; SizeX_mm: 1; SizeZ_mm: 0.6; AEC Category: Q200
C11 C13 C14 C18 C20 C21 C23 C24 = 885012205037: CAP, CERM, 0.1 µF, 16 V, +/- 10%, X7R, 0402; Manufacturer: Wurth Elektronik; Polarized: N; CompType: Capacitor; Value: 0.1uF; U/M: EA; Cap_F: 0.0000001; Tolerance_%: 10; Value1: Unknown; VDC_V: 16; Value2: 16V; TaMin_C: -55; TaMax_C: 125; Cap_Case: 0402; SizeArea_mm2: 0.5; SizeAreaWB_mm2: 3; SizeX_mm: 1; SizeZ_mm: 0.6; AEC Category: Q200
C12 C15 C19 C22 = 06035A221FAT2A: CAP, CERM, 220 pF, 50 V, +/- 1%, C0G/NP0, 0603; Manufacturer: AVX; Polarized: N; CompType: Capacitor; Value: 220pF; U/M: EA; Cap_F: 0.00000000022; Tolerance_%: 1; ESR_ohm: 0.083; Value1: 0.083 ohm; VDC_V: 50; Value2: 50V; TaMin_C: -55; TaMax_C: 125; Cap_Case: 0603; SizeArea_mm2: 1.28; SizeAreaWB_mm2: 4.68; SizeX_mm: 1.6; SizeY_mm: 0.8; AEC Category: Q200
C16 C25 = 885012206081: CAP, CERM, 470 pF, 50 V, +/- 10%, X7R, 0603; Manufacturer: Wurth Elektronik; Polarized: N; CompType: Capacitor; Value: 470pF; U/M: EA; Cap_F: 0.00000000047; Tolerance_%: 10; Value1: Unknown; VDC_V: 50; Value2: 50V; TaMin_C: -55; TaMax_C: 125; Cap_Case: 0603; SizeArea_mm2: 1.28; SizeAreaWB_mm2: 4.68; SizeX_mm: 1.6; SizeY_mm: 0.8; SizeZ_mm: 1; AEC Category: Q200
J7 J8 = CONSMA001-SMD-G: Jack, SMA, PCB, Gold, SMT; Manufacturer: Linx Technologies; SymbolCreator: X0208326
R22 R32 R38 R46 = CRCW060310K0JNEA: RES, 10 k, 5%, 0.1 W, 0603; Manufacturer: Vishay-Dale; CompType: Resistor; Value: 10k; Res_ohm: 10000; Value_Code: 10k0; Tolerance_%: 5; Power_W: 0.1; Value2: 0.1W; VDC_V: 75; TempCo: 200 ppm/C; SizeArea_mm2: 1.28; SizeX_mm: 1.6; SizeY_mm: 0.8; SizeZ_mm: 1; EIA_Code: E24; U/M: EA; AEC Category: Q200
R23 R31 R39 R45 = CRCW06030000Z0EA: RES, 0, 5%, 0.1 W, 0603; Manufacturer: Vishay-Dale; CompType: Resistor; Value: 0; Value_Code: 0000; Tolerance_%: 5; Power_W: 0.1; Value2: 0.1W; VDC_V: 75; TempCo: 200 ppm/C; EIA_Code: E24; U/M: EA; SizeArea_mm2: 1.28; SizeX_mm: 1.6; SizeY_mm: 0.8; SizeZ_mm: 1; AEC Category: Q200
R24 R34 R37 R40 R48 R49 = CMP-0026938-4: RES, 4.7 k, 5%, 0.063 W, 0402; Manufacturer: Vishay-Dale; Power_W: 63mW; TempCo: 200 ppm/C; Value_Code: 4k70; U/M: EA; Value: 4.7k; EIA_Code: E24; SizeX_mm: 1; SizeY_mm: 0.5; SizeZ_mm: 0.6; Value2: 0.063W; CompType: Resistor; VDC_V: 50V; AEC Category: Q200
R25 R41 = CMP-0026880-2: as R6 on sheet TIDA-01401_Interface
R26 R27 R30 R33 R44 R47 = CRCW04020000Z0ED: as R4 on sheet TIDA-01401_Interface
R28 R29 R42 R43 = RC0603FR-0759RL: RES, 59.0, 1%, 0.1 W, 0603; Manufacturer: Yageo America; CompType: Resistor; Value: 59.0; Res_ohm: 59; Value_Code: 59R0; Tolerance_%: 1; Power_W: 0.1; VDC_V: 150; TempCo: 200 ppm/C; SizeArea_mm2: 1.28; SizeX_mm: 1.6; SizeY_mm: 0.8; EIA_Code: E96; U/M: EA; AEC Category: Q200
R35 R36 R50 R51 = CRCW040247R0JNED: RES, 47, 5%, 0.063 W, 0402; Manufacturer: Vishay-Dale; CompType: Resistor; Value: 47; Value_Code: 47R0; Tolerance_%: 5; Power_W: 0.063; Value2: 0.063W; VDC_V: 50; TempCo: 200 ppm/C; SizeArea_mm2: 0.5; SizeX_mm: 1; SizeZ_mm: 0.6; EIA_Code: E24; U/M: EA; AEC Category: Q200
U4 U7 = CMP-0074780-2: 5-V RS-485 Transceivers With +/-16-kV IEC ESD Protection, DGK0008A (VSSOP-8); Manufacturer: Texas Instruments; SizeX_mm: 5.05; SizeY_mm: 3.1; CompType: IC; SizeZ_mm: 1.1; SizeArea_mm2: 15.655; SizeAreaWB_mm2: 35.955; U/M: EA
U5 U6 U8 = SN74LVC2T45YZPR: 2-Bit Dual Supply Transceiver with Configurable Voltage-Level Shifting and 3-State Outputs, YZP0008ADAD (DSBGA-8); Manufacturer: Texas Instruments; SymbolCreator: a0411947; SizeArea_mm2: 2.8125; SizeAreaWB_mm2: 7.3125; SizeX_mm: 1.25; SizeY_mm: 2.25; SizeZ_mm: 0.5; CompType: IC; U/M: EA

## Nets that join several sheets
GND: TIDA-01401_Interface (19 pins), TIDA-01401_PowerSupply (18 pins), TIDA-01401_Transceivers (36 pins)
3V3: TIDA-01401_Interface (R2.1), TIDA-01401_PowerSupply (10 pins), TIDA-01401_Transceivers (8 pins)
3V3_EN_CLK: TIDA-01401_Interface (J3.17), TIDA-01401_Transceivers (R49.1 U8.C2)
3V3_EN_TX: TIDA-01401_Interface (J4.7), TIDA-01401_Transceivers (R37.2 U5.C2)
3V3_ENABLE_5V: TIDA-01401_Interface (J4.20), TIDA-01401_PowerSupply (R19.1 R21.2 U2.C1)
3V3_ENC_PWR_EN: TIDA-01401_Interface (J4.18), TIDA-01401_PowerSupply (R13.1)
3V3_RX_CLK: TIDA-01401_Interface (R7.1), TIDA-01401_Transceivers (U6.C1)
3V3_RX_DATA: TIDA-01401_Interface (J4.12), TIDA-01401_Transceivers (U6.B1)
3V3_TX_CLK: TIDA-01401_Interface (J1.3 J4.1), TIDA-01401_Transceivers (R48.1 U8.B2)
3V3_TX_DATA: TIDA-01401_Interface (R6.2), TIDA-01401_Transceivers (R34.1 U5.B2)
5V: TIDA-01401_PowerSupply (C9.1 R18.2), TIDA-01401_Transceivers (16 pins)
CLK_N: TIDA-01401_Interface (D1.1 J6.7 R4.2), TIDA-01401_Transceivers (C22.1 R43.2 R45.2 R46.2)
CLK_P: TIDA-01401_Interface (D1.2 J6.8 R5.1), TIDA-01401_Transceivers (C19.2 R38.1 R39.2 R42.1)
DATA_N: TIDA-01401_Interface (D2.1 J2.13 J6.4), TIDA-01401_Transceivers (C15.1 R29.2 R31.2 R32.2)
DATA_P: TIDA-01401_Interface (D2.2 J2.5 J6.5), TIDA-01401_Transceivers (C12.2 R22.1 R23.2 R28.1)
VIN: TIDA-01401_Interface (D6.1 J5.1), TIDA-01401_PowerSupply (5 pins)
Vsupply_Enc: TIDA-01401_Interface (J2.4 J6.2), TIDA-01401_PowerSupply (C3.1 R14.2 R15.1 U1.6)

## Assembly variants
001: not fitted C1 C1 C10 C13 C14 C16 C17 C22 C23 C25 D1 D2 J9 J10 R1 R5 R8 R18 R21 R23 R23 R32 R33 R36 R38 R45 R46 TP1 TP2 TP3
